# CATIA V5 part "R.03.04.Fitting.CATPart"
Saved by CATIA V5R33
Part number: R.03.04.Fitting
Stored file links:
  C:\Users\Ryzen5700u\Desktop\robot_cicloidale_singolo\Assieme_robot_cicloidale_singolo\R.03.04.Fitting.CATPart

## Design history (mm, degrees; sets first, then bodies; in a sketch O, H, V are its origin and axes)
Body1 "Solid1" (main body)
  Solid1: solid without history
